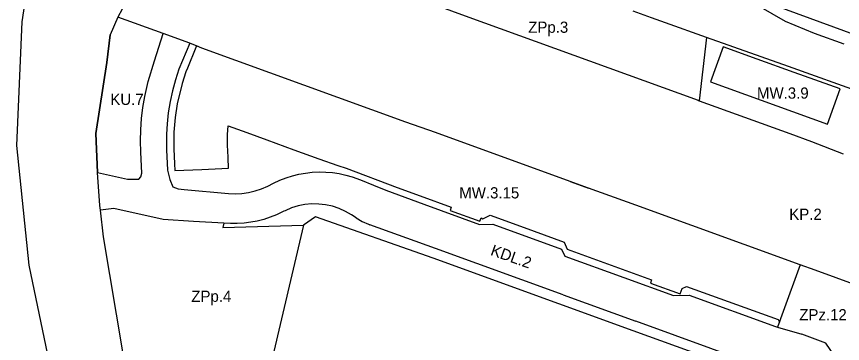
# Model space of a CAD drawing. Extents: x 7428239 to 7429836, y 5549133 to 5550853.
# Drawn here: x 7428326 to 7428694.2, y 5549884.9 to 5550030.9 of the extents above; entities that cross this region are included whole.
import ezdxf

# ---------------------------------------------------------------- set-up
doc = ezdxf.new("R2010")
doc.units = 0
for name, color, linetype in [('LIN_linie rozgraniczające', 7, 'Continuous'), ('LIN_nieprzekraczalna linia zabudowy', 7, 'Continuous'), ('TXT_Oznaczenia Przeznaczenia', 7, 'Continuous')]:
    doc.layers.add(name, color=color, linetype=linetype)

msp = doc.modelspace()

# ---------------------------------------------------------------- linework, layer by layer
at = {"layer": 'LIN_linie rozgraniczające'}
for p, q in [((7428336.04, 5550081.17), (7428328.43, 5550028.45)), ((7428609.06, 5550030.33), (7428600.93, 5550033.25)), ((7428391.42, 5550023.25), (7428371.22, 5550030.6)), ((7428615.34, 5550028.09), (7428609.06, 5550030.33)), ((7428328.43, 5550028.45), (7428325.99, 5549973.28)), ((7428633.54, 5550021.58), (7428615.34, 5550028.09)), ((7428403.18, 5550018.97), (7428391.42, 5550023.25)), ((7428403.18, 5550018.97), (7428398.42, 5550007.33)), ((7428405.82, 5550018.01), (7428403.18, 5550018.97)), ((7428408.66, 5550016.69), (7428405.82, 5550018.01)), ((7428633.54, 5550021.58), (7428630.3, 5549993.32)), ((7428499.58, 5549983.7), (7428408.66, 5550016.69)), ((7428398.42, 5550007.33), (7428396.85, 5550002.58)), ((7428396.85, 5550002.58), (7428395.5, 5549997.77)), ((7428395.5, 5549997.77), (7428394.44, 5549992.88)), ((7428394.44, 5549992.88), (7428393.63, 5549987.95)), ((7428630.3, 5549993.32), (7428670.69, 5549978.61)), ((7428393.63, 5549987.95), (7428393.08, 5549982.98)), ((7428393.08, 5549982.98), (7428392.81, 5549978.44)), ((7428512.72, 5549979.06), (7428499.58, 5549983.7)), ((7428392.81, 5549978.44), (7428392.83, 5549971.31)), ((7428572.82, 5549957.28), (7428512.72, 5549979.06)), ((7428670.69, 5549978.61), (7428680.32, 5549975.11)), ((7428680.32, 5549975.11), (7428694.46, 5549969.64)), ((7428325.99, 5549973.28), (7428331.47, 5549919.94)), ((7428392.83, 5549971.31), (7428393.26, 5549962.23)), ((7428393.26, 5549962.23), (7428394.32, 5549958.13)), ((7428446.14, 5549958.89), (7428449, 5549959.79)), ((7428449, 5549959.79), (7428451.91, 5549960.5)), ((7428451.91, 5549960.5), (7428454.87, 5549961.01)), ((7428454.87, 5549961.01), (7428457.85, 5549961.37)), ((7428457.85, 5549961.37), (7428460.85, 5549961.51)), ((7428460.85, 5549961.51), (7428463.85, 5549961.47)), ((7428463.85, 5549961.47), (7428466.84, 5549961.22)), ((7428466.84, 5549961.22), (7428469.81, 5549960.78)), ((7428469.81, 5549960.78), (7428472.74, 5549960.14)), ((7428472.74, 5549960.14), (7428475.64, 5549959.35)), ((7428475.64, 5549959.35), (7428479.37, 5549957.99)), ((7428394.32, 5549958.13), (7428395.74, 5549954.87)), ((7428437.96, 5549955.18), (7428440.62, 5549956.56)), ((7428440.62, 5549956.56), (7428443.34, 5549957.82)), ((7428443.34, 5549957.82), (7428446.14, 5549958.89)), ((7428479.37, 5549957.99), (7428485.15, 5549955.62)), ((7428485.15, 5549955.62), (7428490.66, 5549953.34)), ((7428572.82, 5549957.28), (7428581.02, 5549954.3)), ((7428395.74, 5549954.87), (7428398.07, 5549953.96)), ((7428398.07, 5549953.96), (7428400.75, 5549953.64)), ((7428400.75, 5549953.64), (7428420.48, 5549951.89)), ((7428420.48, 5549951.89), (7428423.48, 5549951.78)), ((7428423.48, 5549951.78), (7428426.48, 5549951.92)), ((7428426.48, 5549951.92), (7428429.45, 5549952.33)), ((7428429.45, 5549952.33), (7428432.37, 5549953.03)), ((7428432.37, 5549953.03), (7428435.22, 5549953.96)), ((7428435.22, 5549953.96), (7428437.96, 5549955.18)), ((7428490.66, 5549953.34), (7428507.54, 5549947.13)), ((7428602.02, 5549946.68), (7428581.02, 5549954.3)), ((7428391.32, 5549940.31), (7428369.41, 5549945.12)), ((7428507.54, 5549947.13), (7428532.4, 5549937.99)), ((7428675.34, 5549920.07), (7428602.02, 5549946.68)), ((7428439.1, 5549941.27), (7428436.24, 5549940.35)), ((7428441.89, 5549942.38), (7428439.1, 5549941.27)), ((7428444.6, 5549943.67), (7428441.89, 5549942.38)), ((7428445.22, 5549943.99), (7428444.6, 5549943.67)), ((7428404.87, 5549939.35), (7428391.32, 5549940.31)), ((7428418.39, 5549938.7), (7428404.87, 5549939.35)), ((7428418.39, 5549938.7), (7428417.89, 5549936.68)), ((7428417.89, 5549936.68), (7428453.98, 5549937.74)), ((7428421.4, 5549938.55), (7428418.39, 5549938.7)), ((7428424.4, 5549938.54), (7428421.4, 5549938.55)), ((7428427.4, 5549938.69), (7428424.4, 5549938.54)), ((7428430.38, 5549939.05), (7428427.4, 5549938.69)), ((7428433.33, 5549939.61), (7428430.38, 5549939.05)), ((7428436.24, 5549940.35), (7428433.33, 5549939.61)), ((7428453.98, 5549937.74), (7428437.91, 5549869.27)), ((7428512.7, 5549927.32), (7428483.53, 5549937.9)), ((7428532.4, 5549937.99), (7428538.32, 5549938.24)), ((7428538.32, 5549938.24), (7428568.95, 5549927.11)), ((7428569.73, 5549906.63), (7428512.7, 5549927.32)), ((7428568.95, 5549927.11), (7428570.45, 5549923.92)), ((7428570.45, 5549923.92), (7428596.69, 5549914.39)), ((7428331.47, 5549919.94), (7428342.74, 5549865.69)), ((7428675.34, 5549920.07), (7428667.8, 5549899.27)), ((7428681.94, 5549917.67), (7428675.34, 5549920.07)), ((7428700.73, 5549910.8), (7428681.94, 5549917.67)), ((7428596.69, 5549914.39), (7428618.85, 5549906.35)), ((7428569.73, 5549906.63), (7428602.06, 5549894.89)), ((7428618.85, 5549906.35), (7428625.84, 5549906.47)), ((7428667.8, 5549899.27), (7428665.24, 5549892.24)), ((7428658.74, 5549874.33), (7428602.06, 5549894.89)), ((7428690.31, 5549879.89), (7428686.82, 5549885.14))]:
    msp.add_line(p, q, dxfattribs=at)
for points in [[(7428628.82, 5550054.34), (7428631.27, 5550046.51), (7428633.22, 5550044.37), (7428656.8, 5550035.59), (7428668.69, 5550028.81), (7428681.6, 5550023.4), (7428694.78, 5550018.71)], [(7428375.46, 5550038.45), (7428373.05, 5550034.2), (7428371.22, 5550030.6), (7428367.8, 5550022.68)], [(7428507.72, 5550037.84), (7428526.04, 5550031.19), (7428629.86, 5549993.52), (7428630.3, 5549993.32)], [(7428361.31, 5549978.67), (7428366.3, 5550010.42), (7428367.8, 5550022.68)], [(7428362.02, 5549961.25), (7428375.49, 5549958.31), (7428380.48, 5549958.23), (7428381.4, 5549959.37), (7428381.78, 5549960.97), (7428381.36, 5549970.34), (7428381.25, 5549975.34), (7428381.37, 5549980.34), (7428381.74, 5549985.33), (7428382.34, 5549990.29), (7428383.17, 5549995.22), (7428384.7, 5550001.93), (7428387.57, 5550011.16), (7428391.42, 5550023.25)], [(7428704.16, 5549996.32), (7428670.08, 5550008.51), (7428633.54, 5550021.58)], [(7428442.98, 5549712.88), (7428426.27, 5549744.28), (7428414.66, 5549768.71), (7428414.07, 5549769.9), (7428400.61, 5549796.12), (7428392.11, 5549813.98), (7428387.72, 5549824.14), (7428384.1, 5549833.89), (7428381.38, 5549842.53), (7428379.45, 5549849.69), (7428377.68, 5549857.51), (7428376.6, 5549863.19), (7428374.01, 5549878), (7428373.45, 5549881.19), (7428364.82, 5549932.56), (7428363.45, 5549944.39), (7428363.2, 5549946.59), (7428362.02, 5549961.25), (7428361.31, 5549978.67)], [(7428369.41, 5549945.12), (7428363.45, 5549944.39)], [(7428475.25, 5549942.36), (7428472.58, 5549943.92), (7428469.75, 5549945.2), (7428466.81, 5549946.17), (7428463.79, 5549946.84), (7428460.71, 5549947.19), (7428457.61, 5549947.23), (7428454.53, 5549946.94), (7428451.49, 5549946.34), (7428448.53, 5549945.43), (7428445.68, 5549944.22), (7428445.22, 5549943.99)], [(7428477.35, 5549940.99), (7428475.25, 5549942.36)], [(7428477.35, 5549940.99), (7428480.02, 5549939.43), (7428482.85, 5549938.16), (7428483.53, 5549937.9)], [(7428625.84, 5549906.47), (7428664.36, 5549892.5)], [(7428664.36, 5549892.5), (7428665.24, 5549892.24), (7428676.08, 5549889.05)], [(7428686.82, 5549885.14), (7428676.08, 5549889.05)]]:
    msp.add_lwpolyline(points, dxfattribs=at)
at = {"layer": 'LIN_nieprzekraczalna linia zabudowy'}
for points in [[(7428715.06, 5550061.91), (7428701.07, 5550067.07), (7428671.04, 5550078.17), (7428666.19, 5550073.87), (7428645.67, 5550054.64), (7428641.86, 5550044.19), (7428700.72, 5550022.48), (7428715.06, 5550061.91)], [(7428371.22, 5550030.6), (7428367.8, 5550022.68), (7428366.3, 5550010.42), (7428361.31, 5549978.67), (7428362.02, 5549961.25), (7428375.49, 5549958.31), (7428380.48, 5549958.23), (7428381.4, 5549959.37), (7428381.78, 5549960.97), (7428381.36, 5549970.34), (7428381.25, 5549975.34), (7428381.37, 5549980.34), (7428381.74, 5549985.33), (7428382.34, 5549990.29), (7428383.17, 5549995.22), (7428384.7, 5550001.93), (7428387.57, 5550011.16), (7428391.42, 5550023.25), (7428371.22, 5550030.6)], [(7428406.22, 5550017.83), (7428405.88, 5550017), (7428402.16, 5550007.85), (7428401.45, 5550006.18), (7428399.79, 5550001.04), (7428397.56, 5549991.98), (7428396.66, 5549985.86), (7428396.09, 5549979.19), (7428396.08, 5549971.82), (7428396.4, 5549965.13), (7428396.62, 5549962.13), (7428408.61, 5549962.61), (7428420.49, 5549963.19), (7428420.31, 5549967.8), (7428420.15, 5549971.07), (7428420.04, 5549973.2), (7428420.04, 5549978.28), (7428420.27, 5549982.1), (7428428.7, 5549979.05), (7428437.57, 5549975.81), (7428449.54, 5549971.45), (7428460.78, 5549967.37), (7428469.27, 5549964.36), (7428472.87, 5549963.16), (7428495.71, 5549954.55), (7428505.88, 5549950.83), (7428519.78, 5549945.78), (7428519.26, 5549944.34), (7428532.56, 5549939.51), (7428533.08, 5549940.96), (7428533.93, 5549940.65), (7428537.11, 5549942.21), (7428552.36, 5549936.66), (7428570.09, 5549930.23), (7428571.46, 5549927.03), (7428609.08, 5549913.37), (7428608.56, 5549911.94), (7428621.87, 5549907.11), (7428622.73, 5549909.5), (7428624.63, 5549910.43), (7428665.58, 5549895.59), (7428666.05, 5549894.47)], [(7428675.34, 5549920.07), (7428602.02, 5549946.68), (7428581.02, 5549954.3), (7428572.82, 5549957.28), (7428512.72, 5549979.06), (7428499.58, 5549983.7), (7428408.66, 5550016.69), (7428406.22, 5550017.83)], [(7428687.55, 5549982.89), (7428693.16, 5549998.65), (7428672.62, 5550005.96), (7428656.14, 5550011.91), (7428640.93, 5550017.34), (7428635.29, 5550001.67), (7428687.55, 5549982.89)], [(7428602.56, 5549719.6), (7428657.24, 5549870.2), (7428600.92, 5549890.64), (7428567.79, 5549902.64), (7428511.65, 5549922.99), (7428459.3, 5549941.54), (7428453.98, 5549937.74)]]:
    msp.add_lwpolyline(points, dxfattribs=at)

# ---------------------------------------------------------------- texts
at = {"layer": 'TXT_Oznaczenia Przeznaczenia'}
for s, p in [('ZPp.3', (7428554.1, 5550023.61)), ('KU.7', (7428367.79, 5549991.41)), ('MW.3.9', (7428656.08, 5549994.22)), ('MW.3.15', (7428523.35, 5549949.69)), ('KP.2', (7428670.46, 5549940.13)), ('ZPp.4', (7428403.91, 5549903.52)), ('ZPz.12', (7428674.92, 5549895.28))]:
    msp.add_text(s, height=5, dxfattribs=at).set_placement(p)
msp.add_text('KDL.2', height=5, rotation=340.5822, dxfattribs=at).set_placement((7428536.93, 5549924.5))

doc.saveas('drawing.dxf')
